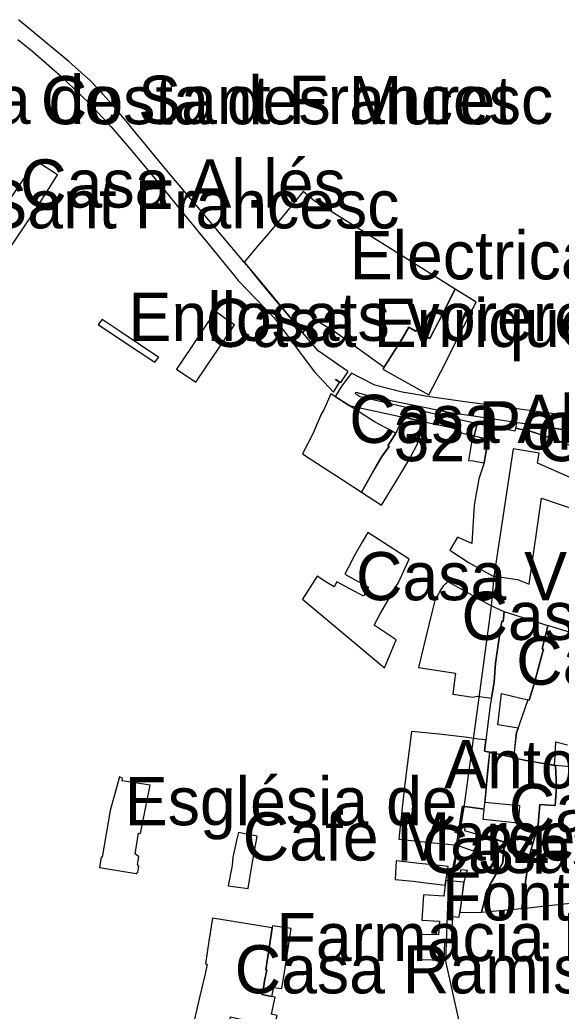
# Model space of a CAD drawing. Extents: x 599451 to 612034, y 4411179 to 4428219.
# Drawn here: x 607851.8 to 607986.7, y 4416234.5 to 4416481.4 of the extents above; entities that cross this region are included whole.
import ezdxf

# ---------------------------------------------------------------- set-up
doc = ezdxf.new("R2010")
doc.units = 0
doc.layers.add('Elements patrimonials', color=7, linetype='Continuous')
doc.layers.add('Muralla_ Perímetre de Protecció', color=7, linetype='Continuous')

msp = doc.modelspace()

# ---------------------------------------------------------------- linework, layer by layer
at = {"layer": 'Elements patrimonials'}
for points in [[(607851.25, 4416476.57), (607855.07, 4416473.46), (607861.76, 4416467.67), (607869, 4416460.76), (607874.49, 4416454.8), (607879.59, 4416448.86), (607887.84, 4416439.01), (607891.69, 4416434.24), (607893.47, 4416432.08), (607895.11, 4416430.07), (607896.15, 4416428.79), (607898.93, 4416425.4), (607902.59, 4416420.92), (607905.23, 4416417.7), (607906.19, 4416416.53), (607906.45, 4416416.26), (607908.29, 4416414.34), (607915.21, 4416407.13), (607923.13, 4416396.55), (607925.22, 4416393.77), (607929.94, 4416388.72), (607931.45, 4416391.08), (607930.44, 4416391.78), (607930.51, 4416391.94), (607931.77, 4416391.14), (607933.61, 4416393.86), (607933.39, 4416393.97), (607926.08, 4416398.98), (607922.32, 4416403.5), (607918.01, 4416408.69), (607914.77, 4416412.57), (607911.53, 4416416.48), (607908.81, 4416419.75), (607907.68, 4416421.09), (607896.17, 4416434.71), (607890.07, 4416441.91), (607886.37, 4416446.36), (607882.16, 4416451.45), (607881.23, 4416452.58), (607878.32, 4416456.1), (607876.03, 4416458.87), (607875.4, 4416459.58), (607872.46, 4416462.95), (607872.28, 4416463.15), (607869.41, 4416466.21), (607863.97, 4416471.05), (607863.47, 4416471.49), (607855.23, 4416478.27), (607851.39, 4416481.44)], [(607987.23, 4416382.96), (607984.2, 4416383.38), (607978.79, 4416384.14), (607975.03, 4416384.67), (607973.09, 4416384.93), (607972.31, 4416385.04), (607963.28, 4416386.26), (607953.93, 4416387.53), (607953.45, 4416387.61), (607947.06, 4416388.67), (607940.21, 4416390.47), (607936.53, 4416392.35), (607934.41, 4416393.44), (607932.19, 4416390.56), (607930.33, 4416387.65), (607933.87, 4416385.4), (607947.29, 4416382.47), (607952.96, 4416381.25), (607958.13, 4416380.15), (607960.59, 4416379.62), (607961.19, 4416378.73), (607965.01, 4416377.78), (607965.34, 4416379.15), (607965.75, 4416380.84), (607938.69, 4416387.09), (607936.62, 4416387.57), (607936.46, 4416387.61), (607935.41, 4416388.26), (607935.53, 4416388.69), (607939.78, 4416387.55), (607959.07, 4416383.64), (607968.84, 4416382.26), (607977.94, 4416380.84), (607992.73, 4416378.51)], [(607987.58, 4416375.98), (607983.46, 4416377.53), (607979.22, 4416378.89), (607975.27, 4416379.74), (607975.11, 4416379), (607965.72, 4416380.85), (607965.02, 4416377.8), (607968.47, 4416376.92), (607967.51, 4416371.08), (607966.15, 4416367.1), (607965.04, 4416360.57), (607964.41, 4416351.04), (607960.84, 4416352.61), (607958.94, 4416349.33), (607963.77, 4416346.24), (607969.6, 4416343), (607975.76, 4416342.07), (607978.67, 4416340.91), (607981.76, 4416362.29), (607995.01, 4416357.87)], [(607989.27, 4416328.74), (607983.4, 4416330.57), (607981.94, 4416324.78), (607982.26, 4416324.69), (607981.13, 4416320.43), (607980.39, 4416317.67), (607979.87, 4416315.7), (607978.72, 4416312.01), (607978.4, 4416312.1), (607975.54, 4416303.93), (607974.77, 4416297.72), (607977.88, 4416296.99), (607978.6, 4416296.9), (607985.03, 4416295.76), (607985.16, 4416298.06), (607985.37, 4416301.59), (607988.3, 4416300.91)]]:
    msp.add_lwpolyline(points, dxfattribs=at)
for points in [[(607855.72, 4416446.32), (607850.92, 4416439.27), (607842.52, 4416426.83), (607848.22, 4416423.03), (607852.97, 4416430.12), (607855.15, 4416433.39), (607859.67, 4416440.47), (607861.17, 4416442.87)], [(607922.38, 4416438.66), (607920.9, 4416436.85), (607916.71, 4416431.82), (607913.2, 4416427.66), (607911.02, 4416425.09), (607907.68, 4416421.09), (607911.54, 4416416.48), (607914.78, 4416412.57), (607918.01, 4416408.69), (607922.33, 4416403.5), (607925.16, 4416406.94), (607930.84, 4416403.37), (607942.56, 4416394.96), (607946.63, 4416401.37), (607948.74, 4416404.91), (607950.41, 4416403.88), (607950.54, 4416404.12), (607953.97, 4416402.11), (607956.9, 4416407.81), (607960.3, 4416414.4), (607952.47, 4416419.29), (607925.1, 4416436.4)], [(607960.3, 4416414.4), (607956.9, 4416407.81), (607955.47, 4416405.02), (607953.97, 4416402.11), (607950.54, 4416404.12), (607950.41, 4416403.88), (607948.74, 4416404.91), (607946.85, 4416401.74), (607942.24, 4416394.41), (607946.41, 4416392.09), (607953.69, 4416388.05), (607957.73, 4416395.88), (607960.8, 4416401.95), (607965.52, 4416411.13)], [(607890.84, 4416394.46), (607895.6, 4416391.21), (607898.06, 4416394.79), (607901.33, 4416399.66), (607903.59, 4416403), (607905.26, 4416405.49), (607904.12, 4416406.25), (607900.49, 4416408.76), (607899.96, 4416408.02), (607897.71, 4416404.72), (607896.66, 4416403.17), (607894.43, 4416399.84)], [(607872.32, 4416406.81), (607871.28, 4416405.55), (607877.1, 4416401.69), (607885.42, 4416396.17), (607886.4, 4416397.4), (607886.18, 4416397.55), (607877.27, 4416403.49)], [(607933.88, 4416385.4), (607929.29, 4416388.32), (607927.5, 4416384.33), (607926.94, 4416383.37), (607926.47, 4416382.27), (607924.79, 4416378.31), (607922.25, 4416373.35), (607925.82, 4416371.02), (607932.35, 4416366.78), (607936.88, 4416363.8), (607940.25, 4416369.68), (607941.97, 4416372.71), (607943.8, 4416375.21), (607943.47, 4416375.37), (607945.47, 4416378.54), (607940.19, 4416381.36)], [(607947.3, 4416382.47), (607945.47, 4416378.54), (607943.47, 4416375.37), (607943.8, 4416375.21), (607941.97, 4416372.71), (607940.25, 4416369.68), (607936.88, 4416363.8), (607941.94, 4416360.55), (607945.51, 4416366.41), (607948.93, 4416372.23), (607951.08, 4416376.16), (607950.7, 4416376.32), (607952.97, 4416381.25)], [(608022.61, 4416373.81), (608015.61, 4416374.91), (607992.73, 4416378.51), (607977.94, 4416380.84), (607975.54, 4416381.11), (607975.27, 4416379.74), (607979.22, 4416378.89), (607983.46, 4416377.53), (607990.75, 4416374.76), (607994.41, 4416373.31), (608002.62, 4416370.05), (608016.29, 4416362.91), (608022.62, 4416373.42)], [(607965.02, 4416377.78), (607964.44, 4416376.68), (607963.59, 4416371.69), (607964.82, 4416371.57), (607965.55, 4416371.43), (607967.51, 4416371.08), (607968.47, 4416376.92)], [(607938.5, 4416353.75), (607937.17, 4416351.48), (607935.25, 4416348.19), (607933.6, 4416344.98), (607932.78, 4416343.39), (607938.7, 4416340.15), (607937.4, 4416337.88), (607930.79, 4416341.51), (607930.1, 4416340.2), (607930.1, 4416340.2), (607928.29, 4416341.33), (607925.88, 4416342.86), (607922.24, 4416337.12), (607932.44, 4416328.58), (607942.64, 4416320.04), (607945.6, 4416327.05), (607940.04, 4416330.68), (607941.58, 4416333.52), (607946.1, 4416341.27), (607948.82, 4416347.09)], [(607972.51, 4416333.98), (607968.9, 4416335.64), (607958.36, 4416341.56), (607958.05, 4416341.18), (607957.27, 4416340.39), (607956.5, 4416339.35), (607956.07, 4416338.51), (607955.26, 4416337.17), (607954.63, 4416334.54), (607952.87, 4416327.39), (607951.16, 4416320.15), (607960.36, 4416318.69), (607960.12, 4416316.89), (607959.66, 4416313.5), (607964.73, 4416312.76), (607965.76, 4416312.98), (607969.29, 4416312.47), (607969.99, 4416316.59), (607970.35, 4416321.18), (607971.01, 4416325.77), (607971.31, 4416327.99), (607971.9, 4416331.65), (607972.2, 4416331.61)], [(607972.49, 4416333.99), (607972.2, 4416331.61), (607971.9, 4416331.65), (607971.31, 4416327.99), (607971.01, 4416325.77), (607970.35, 4416321.18), (607969.99, 4416316.59), (607969.29, 4416312.47), (607969.01, 4416310.79), (607968.24, 4416304.72), (607967.91, 4416302.03), (607967.54, 4416299.33), (607971.85, 4416298.38), (607974.77, 4416297.72), (607975.02, 4416299.09), (607975.54, 4416303.93), (607976.08, 4416305.06), (607974.96, 4416305.23), (607970.86, 4416305.86), (607971.84, 4416313.67), (607978.72, 4416312.01), (607979.72, 4416315.22), (607980.13, 4416316.68), (607981.47, 4416321.75), (607982.26, 4416324.69), (607981.94, 4416324.78), (607983.38, 4416330.52), (607979.87, 4416331.64)], [(607967.92, 4416302.11), (607966.07, 4416302.29), (607964.45, 4416302.52), (607963.34, 4416302.67), (607956.3, 4416303.56), (607949.35, 4416304.24), (607947.63, 4416290.51), (607946.78, 4416282.85), (607946.21, 4416277.37), (607954.88, 4416276.49), (607957.65, 4416276.2), (607960.62, 4416275.86), (607962.08, 4416285.57), (607967.52, 4416284.86), (607967.67, 4416286.44), (607967.89, 4416288.85), (607968.25, 4416292.89), (607968.63, 4416297.06), (607968.87, 4416299.07), (607967.54, 4416299.33)], [(607968.93, 4416299.03), (607968.86, 4416299.04), (607968, 4416290.15), (607967.67, 4416286.58), (607976.27, 4416285.75), (607975.95, 4416281.38), (607967.25, 4416282.27), (607967.52, 4416284.86), (607962.08, 4416285.57), (607961.69, 4416280.94), (607962.79, 4416280.71), (607962.79, 4416280.67), (607962.61, 4416279.55), (607962.62, 4416279.55), (607972.58, 4416276.64), (607972.14, 4416271.55), (607968.93, 4416265.99), (607967.77, 4416262.74), (607966.81, 4416259.22), (607976.85, 4416260.16), (607977.08, 4416261.53), (607978.67, 4416273.06), (607980.92, 4416280.91), (607981.11, 4416283.1), (607981.35, 4416286.04), (607984.95, 4416285.77), (607985.22, 4416285.74), (607985.53, 4416290.35), (607985.29, 4416295.71), (607981.79, 4416296.33), (607977.88, 4416296.99), (607975.11, 4416297.52)], [(607996.88, 4416277.94), (607996.25, 4416287.14), (607996.32, 4416293.65), (607995.69, 4416293.81), (607991.47, 4416294.84), (607989.19, 4416295.41), (607989.18, 4416295.41), (607985.03, 4416295.76), (607985.29, 4416295.71), (607985.53, 4416290.35), (607985.22, 4416285.74), (607984.95, 4416285.77), (607981.35, 4416286.04), (607981.11, 4416283.1), (607980.92, 4416280.91), (607978.67, 4416273.06), (607977.08, 4416261.53), (607976.85, 4416260.16), (607986.59, 4416261.16), (607998.22, 4416262.35), (607997.49, 4416267.79), (607997.21, 4416273.15)], [(607876.63, 4416292.89), (607874.25, 4416284.54), (607872.26, 4416272.88), (607872.04, 4416272.91), (607871.6, 4416270.34), (607880.78, 4416268.81), (607881.19, 4416269.19), (607881.4, 4416270.66), (607881.09, 4416271.09), (607881.39, 4416272.97), (607880.48, 4416273.73), (607881.34, 4416278.89), (607881.84, 4416278.82), (607884.27, 4416290.83), (607877.27, 4416291.91), (607877.33, 4416292.55)], [(607903.7, 4416265.73), (607908.67, 4416265.13), (607909.45, 4416269.74), (607910.9, 4416278.1), (607906.23, 4416279.02), (607905.86, 4416277.35), (607904.88, 4416272.87), (607904.65, 4416270.84)], [(607961.46, 4416259.12), (607966.81, 4416259.22), (607967.77, 4416262.74), (607968.93, 4416265.99), (607970.58, 4416268.86), (607972.14, 4416271.56), (607972.18, 4416272.06), (607972.58, 4416276.6), (607970.05, 4416277.47), (607966.71, 4416278.4), (607964.86, 4416274.37), (607960.62, 4416275.86), (607960.15, 4416272.7), (607959.38, 4416268.91), (607961.46, 4416268.58), (607961.73, 4416269.84), (607963.23, 4416269.63), (607962.39, 4416266.71)], [(607956.25, 4416270.79), (607951.32, 4416271.35), (607945.57, 4416271.95), (607945.29, 4416267.34), (607949.82, 4416266.89), (607952.93, 4416266.54), (607955.73, 4416266.21), (607957.81, 4416265.95), (607958.5, 4416270.56)], [(607957.97, 4416267.06), (607957.8, 4416265.94), (607957.46, 4416263.19), (607952.34, 4416263.49), (607951.98, 4416257.2), (607956.33, 4416256.95), (607956.13, 4416253.57), (607951.79, 4416253.68), (607951.57, 4416247.44), (607957.52, 4416247.25), (607957.68, 4416251.67), (607959.41, 4416251.64), (607959.55, 4416255.79), (607959.56, 4416256.36), (607959.58, 4416257.18), (607959.62, 4416258.15), (607961.3, 4416257.98), (607961.89, 4416262.31), (607962.39, 4416266.71)], [(607899.76, 4416257.75), (607898.89, 4416252.02), (607898.07, 4416246.3), (607898.44, 4416246.23), (607897.99, 4416243.83), (607896.54, 4416237.94), (607894.74, 4416230.1), (607901.22, 4416220.22), (607904.26, 4416233.12), (607915.18, 4416230.68), (607915.87, 4416233.5), (607914.47, 4416233.8), (607915.37, 4416238.07), (607914.58, 4416238.22), (607912.06, 4416238.7), (607912.58, 4416240.83), (607912.73, 4416242.14), (607913.31, 4416244.76), (607913.07, 4416244.82), (607914.66, 4416255.29)], [(607914.74, 4416255.83), (607914.66, 4416255.29), (607913.72, 4416249.04), (607913.49, 4416247.61), (607913.07, 4416244.82), (607913.31, 4416244.76), (607912.73, 4416242.14), (607912.58, 4416240.83), (607912.06, 4416238.7), (607914.58, 4416238.22), (607915.09, 4416240.48), (607917.09, 4416240.21), (607917.7, 4416244.29), (607918.89, 4416251.84), (607919.42, 4416255.14)]]:
    msp.add_lwpolyline(points, close=True, dxfattribs=at)
at = {"layer": 'Muralla_ Perímetre de Protecció'}
msp.add_lwpolyline([(608016.61, 4416355.38), (607980.82, 4416371.07), (607981.19, 4416373.51), (607974.7, 4416374.59), (607969.91, 4416342.8), (607969.21, 4416335.44), (607966.83, 4416317.58), (607964.76, 4416302.32), (607962.39, 4416285.37), (607961.69, 4416280.94), (607960.01, 4416270.24), (607958.45, 4416262.96), (607957.83, 4416246.98), (607968.87, 4416197.32)], dxfattribs=at)

# ---------------------------------------------------------------- texts
at = {"layer": 'Elements patrimonials'}
for s, p in [('Església de Sant Francesc', (607793.82, 4416455.52)), ('Costa des Muret', (607856.99, 4416455.43)), ('Casa Al.lés', (607851.84, 4416434.68)), ('Claustre Sant Francesc', (607778.7, 4416429.5)), ('Electrica Vella', (607933.99, 4416416.81)), ('Enllosats voreres', (607878.84, 4416401.49)), ('Casa Enrique Andreu', (607898.05, 4416399.98)), ('Casa Alberti-Osuna', (607933.86, 4416376.06)), ("Pont d'es General", (607966.03, 4416374.43)), ('32    Casa', (607944.92, 4416371.51)), ('Casa Vidal', (607935.53, 4416336.89)), ('Casa Albertí', (607961.83, 4416327.01)), ('Casa Albertí', (607975.46, 4416315.85)), ('Antonia de Olives', (607957.54, 4416290.05)), ('Església de', (607877.93, 4416280.85)), ('Casa Guillermo', (607973.61, 4416279.13)), ('Cafe Marce', (607907.3, 4416272.07)), ('Casa Galmes', (607951.89, 4416268.95)), ('34-36   Casa', (607965.98, 4416268.76)), ('Font de Sant Roc', (607956.98, 4416257.15)), ('Farmacia Mir', (607915.74, 4416247.02)), ('Casa Ramis i Ramis', (607905.3, 4416238.98))]:
    msp.add_text(s, height=12, dxfattribs=at).set_placement(p)

doc.saveas('drawing.dxf')
